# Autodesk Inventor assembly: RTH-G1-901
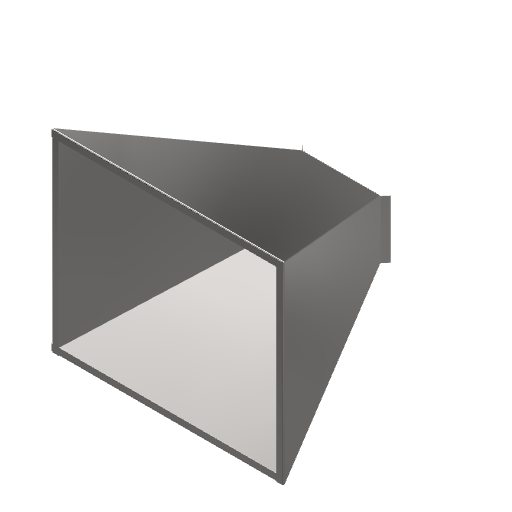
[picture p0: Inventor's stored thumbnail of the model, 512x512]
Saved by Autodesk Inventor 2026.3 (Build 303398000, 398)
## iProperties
Part Number: RTH-G1-901
Material: Generic
Description: HEX BOLT M10x20 8.8 ZP
Part Number: RTH-G1-903
Description: FLAT WASHER M10 ZP
Part Number: RTH-G1-902
Description: HEX NUT M10 8 ZP
Created: 2026-09
Part Number: RTH-G1-000
Document SubType Name: Assembly
Designer: mykol
Project: RTH-G1
Description: HOPPER 1200x1000 to 400x300 H900
Author: mykol
RuthenConfigId: RTH-G1-A-b1a1fe2e
RuthenRuleSet: 1.0.0
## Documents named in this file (5)
- C:\Ruthen\InventorFlagship\output\e2e\RTH-G1\Models\RTH-G1-000.iam
- C:\Ruthen\InventorFlagship\output\e2e\RTH-G1\Models\RTH-G1-101.ipt
- C:\Ruthen\InventorFlagship\output\e2e\RTH-G1\Models\RTH-G1-102.ipt
- C:\Ruthen\InventorFlagship\output\e2e\RTH-G1\Models\RTH-G1-103.ipt
- C:\Ruthen\InventorFlagship\output\e2e\RTH-G1\Models\RTH-G1-104.ipt
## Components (7 placed, 7 different names)
1. RTH-G1-101:1
2. RTH-G1-102:1
3. RTH-G1-103:1
4. RTH-G1-104:1
5. RTH-G1-901:1
6. RTH-G1-902:1
7. RTH-G1-903:1
